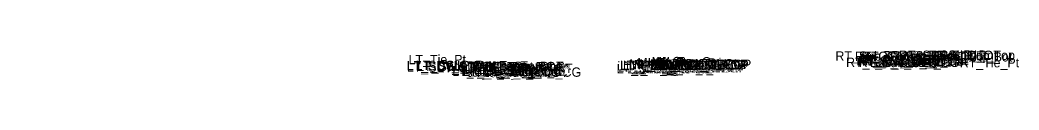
# Model space of a CAD drawing. Extents: x 0 to 4229, y -1 to 9523.
# Drawn here: x 2000 to 2215, y 8999.6 to 9006 of the extents above; entities that cross this region are included whole.
import ezdxf

# ---------------------------------------------------------------- set-up
doc = ezdxf.new("R2010")
doc.units = 0
doc.layers.add('Default', color=7, linetype='Continuous')

msp = doc.modelspace()

# ---------------------------------------------------------------- texts
at = {"layer": 'Default'}
for s, height, p in [('RT_SDWK_Out_Top', 2, (2189.19, 9003.88)), ('RT_Shld_O', 2, (2195.54, 9003.86)), ('CSLP_Pnt', 2, (2197.87, 9003.9)), ('LT_Tie_Pt', 2, (2083.65, 9002.96)), ('LT_PV1_OEEOP', 2, (2129.12, 9001.74)), ('LT_PV1_IEEOP', 2, (2129.77, 9001.74)), ('LT_PV1_PGL', 2, (2131.03, 9001.86)), ('MI_Face In', 2, (2131.15, 9002.03)), ('MI_Bot In', 2, (2132.13, 9001.86)), ('MI_Top In', 2, (2132.86, 9002.28)), ('RT_PV2_OEEOP', 2, (2135.74, 9001.8)), ('MI_Crown', 2, (2135.94, 9002.52)), ('RT_PV1_OEEOP', 2, (2136.31, 9001.92)), ('RT_PV2_IEEOP', 2, (2136.39, 9001.8)), ('MI_Face Out', 2, (2136.74, 9002.22)), ('MI_Top Out', 2, (2136.95, 9002.47)), ('RT_PV1_IEEOP', 2, (2136.96, 9001.92)), ('RT_PV2_PGL1', 2, (2137.32, 9001.8)), ('RT_PV2_PGL', 2, (2137.65, 9001.8)), ('MI_Bot Out', 2, (2137.74, 9002.05)), ('RT_PV1_PGL', 2, (2138.22, 9002.05)), ('RT_Sub_Trench_Out_DLT', 2, (2175.52, 9003.71)), ('RT_Sub_OEOT_CG', 2, (2177.82, 9002.36)), ('RT_CG_Top_Face', 2, (2179.71, 9003.66)), ('RT_CG1_Shelf_Out', 2, (2180, 9002.69)), ('RT_CG_Bot_IE', 2, (2180.37, 9002.61)), ('RT_Sub_OEOT', 2, (2180.53, 9002.32)), ('RT_PV2_OEOT', 2, (2180.63, 9002.94)), ('RT_PV3_OEOT', 2, (2180.63, 9002.69)), ('RT_CG_Top_Gut', 2, (2180.69, 9003.16)), ('RT_PV1_OEOT', 2, (2181.19, 9003.19)), ('RT_CG_Top_BOC', 2, (2181.24, 9003.66)), ('RT_CG_Bot_BOC', 2, (2181.27, 9002.67)), ('RT_Sub_OEOP', 2, (2183.81, 9002.44)), ('RT_SDWK_In_Top', 2, (2185.81, 9003.78)), ('RT_SDWK_In_Bot', 2, (2185.84, 9003.44)), ('RT_SDWK_Out_Bot', 2, (2189.22, 9003.54)), ('RT_Tie_Pt', 2, (2202.28, 9002.28)), ('LT_SDWK_Out_Top', 2, (2083.24, 9001.67)), ('LT_SDWK_Out_Bot', 2, (2083.27, 9001.33)), ('LT_CSLP_Pnt', 2, (2085.17, 9001.69)), ('LT_Sub_Trench_Out_DLT', 2, (2085.48, 9001.5)), ('LT_SDWK_In_Top', 2, (2089.86, 9001.57)), ('LT_SDWK_In_Bot', 2, (2089.89, 9001.23)), ('LT_CG1_Shelf_Out', 2, (2093.05, 9000.43)), ('LT_CG_Top_Face', 2, (2094.76, 9001.45)), ('LT_CG_Top_BOC', 2, (2095.28, 9001.45)), ('LT_CG_Bot_BOC', 2, (2095.31, 9000.44)), ('LT_CG_Top_Gut', 2, (2095.74, 9000.95)), ('LT_Sub_OEOP', 2, (2096.35, 9000.17)), ('LT_Sub_OEOT_CG', 2, (2096.87, 9000.25)), ('LT_CG_Bot_IE', 2, (2099.41, 9000.5)), ('LT_Sub_OEOT', 2, (2099.58, 9000.21)), ('LT_PV2_OEOT', 2, (2099.67, 9000.84)), ('LT_PV3_OEOT', 2, (2099.67, 9000.59)), ('LT_PV1_OEOT', 2, (2100.24, 9001.09)), ('LT_Sub_OEEOP', 2, (2128.46, 9000.99)), ('LT_PV2_OEEOP', 2, (2128.56, 9001.61)), ('LT_PV3_OEEOP', 2, (2128.56, 9001.36)), ('LT_PV2_IEEOP', 2, (2129.2, 9001.61)), ('LT_PV2_PGL1', 2, (2130.13, 9001.61)), ('LT_PV3_PGL1', 2, (2130.13, 9001.36)), ('LT_PV2_PGL', 2, (2130.46, 9001.61)), ('LT_PV4_PGL', 2, (2130.46, 9000.99)), ('RT_Sub_OEEOP', 2, (2135.65, 9001.17)), ('RT_PV3_OEEOP', 2, (2135.74, 9001.55)), ('RT_PV3_PGL1', 2, (2137.32, 9001.55)), ('RT_PV4_PGL', 2, (2137.65, 9001.17)), ('-', 0.0001, (2000, 9000)), ('-', 0.0001, (2000, 9000)), ('-', 0.0001, (2000, 9000)), ('-', 0.0001, (2000, 9000)), ('-', 0.0001, (2000, 9000)), ('-', 0.0001, (2000, 9000)), ('-', 0.0001, (2000, 9000))]:
    msp.add_text(s, height=height, dxfattribs=at).set_placement(p)

doc.saveas('drawing.dxf')
